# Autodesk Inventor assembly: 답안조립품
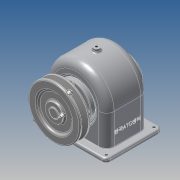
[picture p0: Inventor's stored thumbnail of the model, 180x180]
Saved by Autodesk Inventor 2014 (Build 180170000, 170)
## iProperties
Created: 2016-01
Part Number: 답안조립품
Document SubType Name: Assembly
Designer: user
Author: user
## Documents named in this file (14)
- C:\Users\user\Desktop\460106V1007\답안조립품.iam
- C:\Users\user\Desktop\460106V1007\본체.ipt
- C:\Users\user\Desktop\460106V1007\뒤커버.ipt
- C:\Users\user\Desktop\460106V1007\앞커버.ipt
- C:\Users\user\Desktop\460106V1007\축.ipt
- C:\Users\user\Desktop\460106V1007\키 - 6 x 6 x 22.ipt
- C:\Users\user\Desktop\460106V1007\볼트 M3 x 8.ipt
- C:\Users\user\Desktop\460106V1007\볼트 M3 x 10.ipt
- C:\Users\user\Desktop\460106V1007\키 - 5 x 5 x 18.ipt
- C:\Users\user\Desktop\460106V1007\오일씰 28 40 8.ipt
- C:\Users\user\Desktop\460106V1007\베어링 6203.ipt
- C:\Users\user\Desktop\460106V1007\스퍼기어.ipt
- C:\Users\user\Desktop\460106V1007\V-벨트풀리.ipt
- C:\Users\user\Desktop\460106V1007\멈춤나사 - M4x10.ipt
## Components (9 placed, 3 different names)
1. V-벨트풀리:1 — Insert:13, Mate:6, Mate:7
2. ISO 4762 M3 x 8:1 — Insert:5
3. ISO 4762 M3 x 8:2
4. ISO 4762 M3 x 8:3
5. ISO 4762 M3 x 8:4
6. ISO 4762 M3 x 10:1 — Insert:4
7. ISO 4762 M3 x 10:2
8. ISO 4762 M3 x 10:3
9. ISO 4762 M3 x 10:4
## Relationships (5: Insert 3, Mate 2)
- Insert:4: ISO 4762 M3 x 10:1
- Insert:5: ISO 4762 M3 x 8:1
- Insert:13: V-벨트풀리:1
- Mate:6: V-벨트풀리:1
- Mate:7: V-벨트풀리:1
